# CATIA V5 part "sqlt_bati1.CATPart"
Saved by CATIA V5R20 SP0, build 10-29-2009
Part number: sqlt_bati
Publications: "rayon_bati", "rayon_pivot", "hauteur_bati", "hauteur_pivot", "rayon_trou", "Plan.1", "Point.1", "Droite.1", "Point.2", "Point.3", "Point.4", "Point.5", "Point.6", "Point.7", "Point.8", "Plan.2", "Point.10", "Plan de contact avec la poulie principale"
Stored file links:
  D:\ecole\thinkmotion\sqlt_bati1.CATPart
  D:\ecole\thinkmotion\sqlt_eolienne.CATProduct
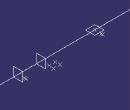
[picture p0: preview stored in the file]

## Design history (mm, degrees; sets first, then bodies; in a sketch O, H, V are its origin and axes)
Parameters
  rayon_bati = 50 mm {= External.rayon_bati}
  `rayon_pivot-rayon_bati` = 30 mm {= External.rayon_pivot_bati -External.rayon_bati}
  hauteur_bati = 300 mm {= External.hauteur_bati}
  hauteur_pivot = 40 mm {= External.hauteur_pivot}
  rayon_trou = 40 mm {= External.rayon_bati -10mm}
External parameters (linked from other documents)
  External.rayon_bati = 50 mm
  External.rayon_pivot_bati = 80 mm
  External.hauteur_bati = 300 mm
  External.hauteur_pivot = 40 mm
  `External.profondeur_perçage` = 25 mm
  External.longueur_jusque_pivot_soutient = 100 mm
  External.hauteur_pivot_soutient = 20 mm
Set1 "squelette_bati"
  Plane1: type Offset, RefPlane xy-plane, Offset 0
  Point1: (0, 0, 0)
  Line1 "Axe de rotation": type PtDir, RefPoint Point1, Direction yz-plane, Start 0, End 20
  Point2: (0, 40 {= External.rayon_bati -10mm}, 0)
  Point3: (0, 50 {= rayon_bati}, 0)
  Point4: (300 {= hauteur_bati}, 50 {= rayon_bati}, 0)
  Point5: (300 {= hauteur_bati}, 80 {= rayon_bati +`rayon_pivot-rayon_bati`}, 0)
  Point6: (340 {= hauteur_bati +hauteur_pivot}, 80 {= rayon_bati +`rayon_pivot-rayon_bati`}, 0)
  Point7: (340 {= hauteur_bati +hauteur_pivot}, 50 {= rayon_bati}, 0)
  Point8: (485 {= hauteur_pivot +hauteur_bati +`External.profondeur_perçage` +External.longueur_jusque_pivot_soutient +External.hauteur_pivot_soutient}, 50 {= rayon_bati}, 0)
  Plane2 "Plan de contact avec le support pale": type Offset, RefPlane yz-plane, Offset 340 {= hauteur_bati +hauteur_pivot}
  Point9: (485 {= hauteur_bati +hauteur_pivot +`External.profondeur_perçage` +External.longueur_jusque_pivot_soutient +External.hauteur_pivot_soutient}, 40 {= External.rayon_bati -10mm}, 0)
  Plane3 "Plan de contact avec la poulie principale": type Offset, RefPlane Plane2, Offset 145 {= `External.profondeur_perçage` +External.longueur_jusque_pivot_soutient +External.hauteur_pivot_soutient}
Body1 (main body)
